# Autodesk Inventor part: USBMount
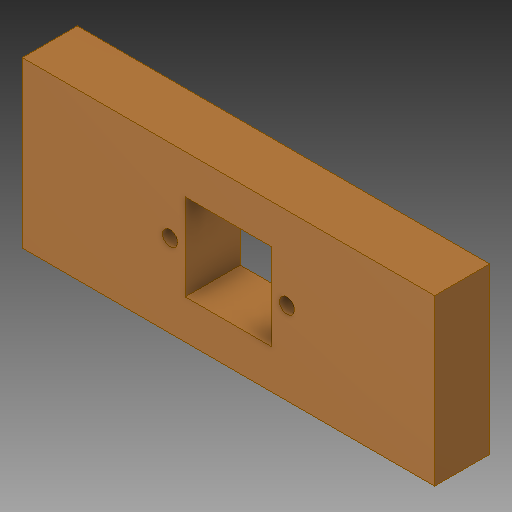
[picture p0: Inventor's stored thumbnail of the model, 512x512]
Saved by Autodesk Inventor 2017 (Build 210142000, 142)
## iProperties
Created: 2017-05
Part Number: USBMount
Material: Generic
Document SubType Name: Modeling
Designer: Savy
Density: 1 g/cm^3
Appearance: Default
Author: Savy
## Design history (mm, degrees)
feature "SOLID1"
body "Solid1"
